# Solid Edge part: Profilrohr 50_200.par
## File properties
Username: ahadarics
Dokumentum tartalom típus: 0
Author: ahadarics
Last saved by: ahadarics
Revision: 84
Sűrűség: 0,000 kg/m^3
Pontosság: 0,990
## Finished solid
Body 1: solid body, 175 faces, 519 edges, 346 vertices.
  Faces by surface: cylinder 107, plane 68
  Edges by curve: line 305, circle 214
Bounding box of the edges (mm): 60.200 x 60.200 x 244.000, from (-30.1, -30.1, -209.5) to (30.1, 30.1, 34.5).
Cylindrical faces by radius (mm): R0.1 x16, R0.2 x30, R0.5 x28, R1 x8, R3.75 x8, R5 x4, R6 x4, R25 x1, R27 x8
Planar faces by outward normal: +x 6, +y 6, +z 1, -x 4, -y 4, -z 1, oblique 46
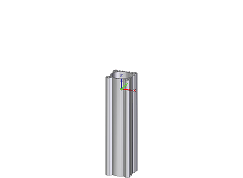
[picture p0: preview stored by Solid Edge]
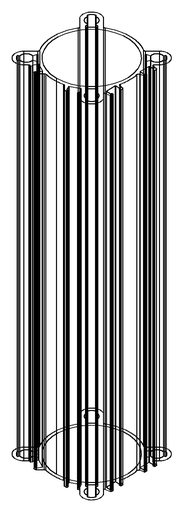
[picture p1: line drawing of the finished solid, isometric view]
